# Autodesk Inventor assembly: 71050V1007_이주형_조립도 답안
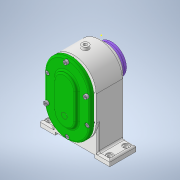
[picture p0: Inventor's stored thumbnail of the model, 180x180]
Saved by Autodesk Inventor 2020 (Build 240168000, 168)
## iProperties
Created: 2021-05
Part Number: 71050V1007_이주형_조립도 답안
Document SubType Name: Assembly
Designer: Owner
Author: Owner
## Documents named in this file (15)
- C:\Users\Owner\Desktop\710507V1007_이주형\71050V1007_이주형_조립도 답안.iam
- C:\Users\Owner\Desktop\710507V1007_이주형\710507V1007_이주형_본체.ipt
- C:\Users\Owner\Desktop\710507V1007_이주형\베어링 6001.ipt
- 베어링 6001.ipt
- C:\Users\Owner\Desktop\710507V1007_이주형\커버 A.ipt
- C:\Users\Owner\Desktop\710507V1007_이주형\축 A.ipt
- C:\Users\Owner\Desktop\710507V1007_이주형\칼라.ipt
- C:\Users\Owner\Desktop\710507V1007_이주형\베어링 6002.ipt
- 베어링 6002.ipt
- C:\Users\Owner\Desktop\710507V1007_이주형\커버 B.ipt
- C:\Users\Owner\Desktop\710507V1007_이주형\오일 실 12 22 7.ipt
- C:\Users\Owner\Desktop\710507V1007_이주형\축 B.ipt
- C:\Users\Owner\Desktop\710507V1007_이주형\키 5 x 5 x 12.ipt
- C:\Users\Owner\Desktop\710507V1007_이주형\키 4 x 4 x 12.ipt
- C:\Users\Owner\Desktop\710507V1007_이주형\볼트 M4.ipt
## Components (1 placed, 1 different names)
1. 710507V1007_이주형_본체:1 — 플러쉬:1
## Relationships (1: Flush 1)
- 플러쉬:1 [Flush]: 710507V1007_이주형_본체:1
